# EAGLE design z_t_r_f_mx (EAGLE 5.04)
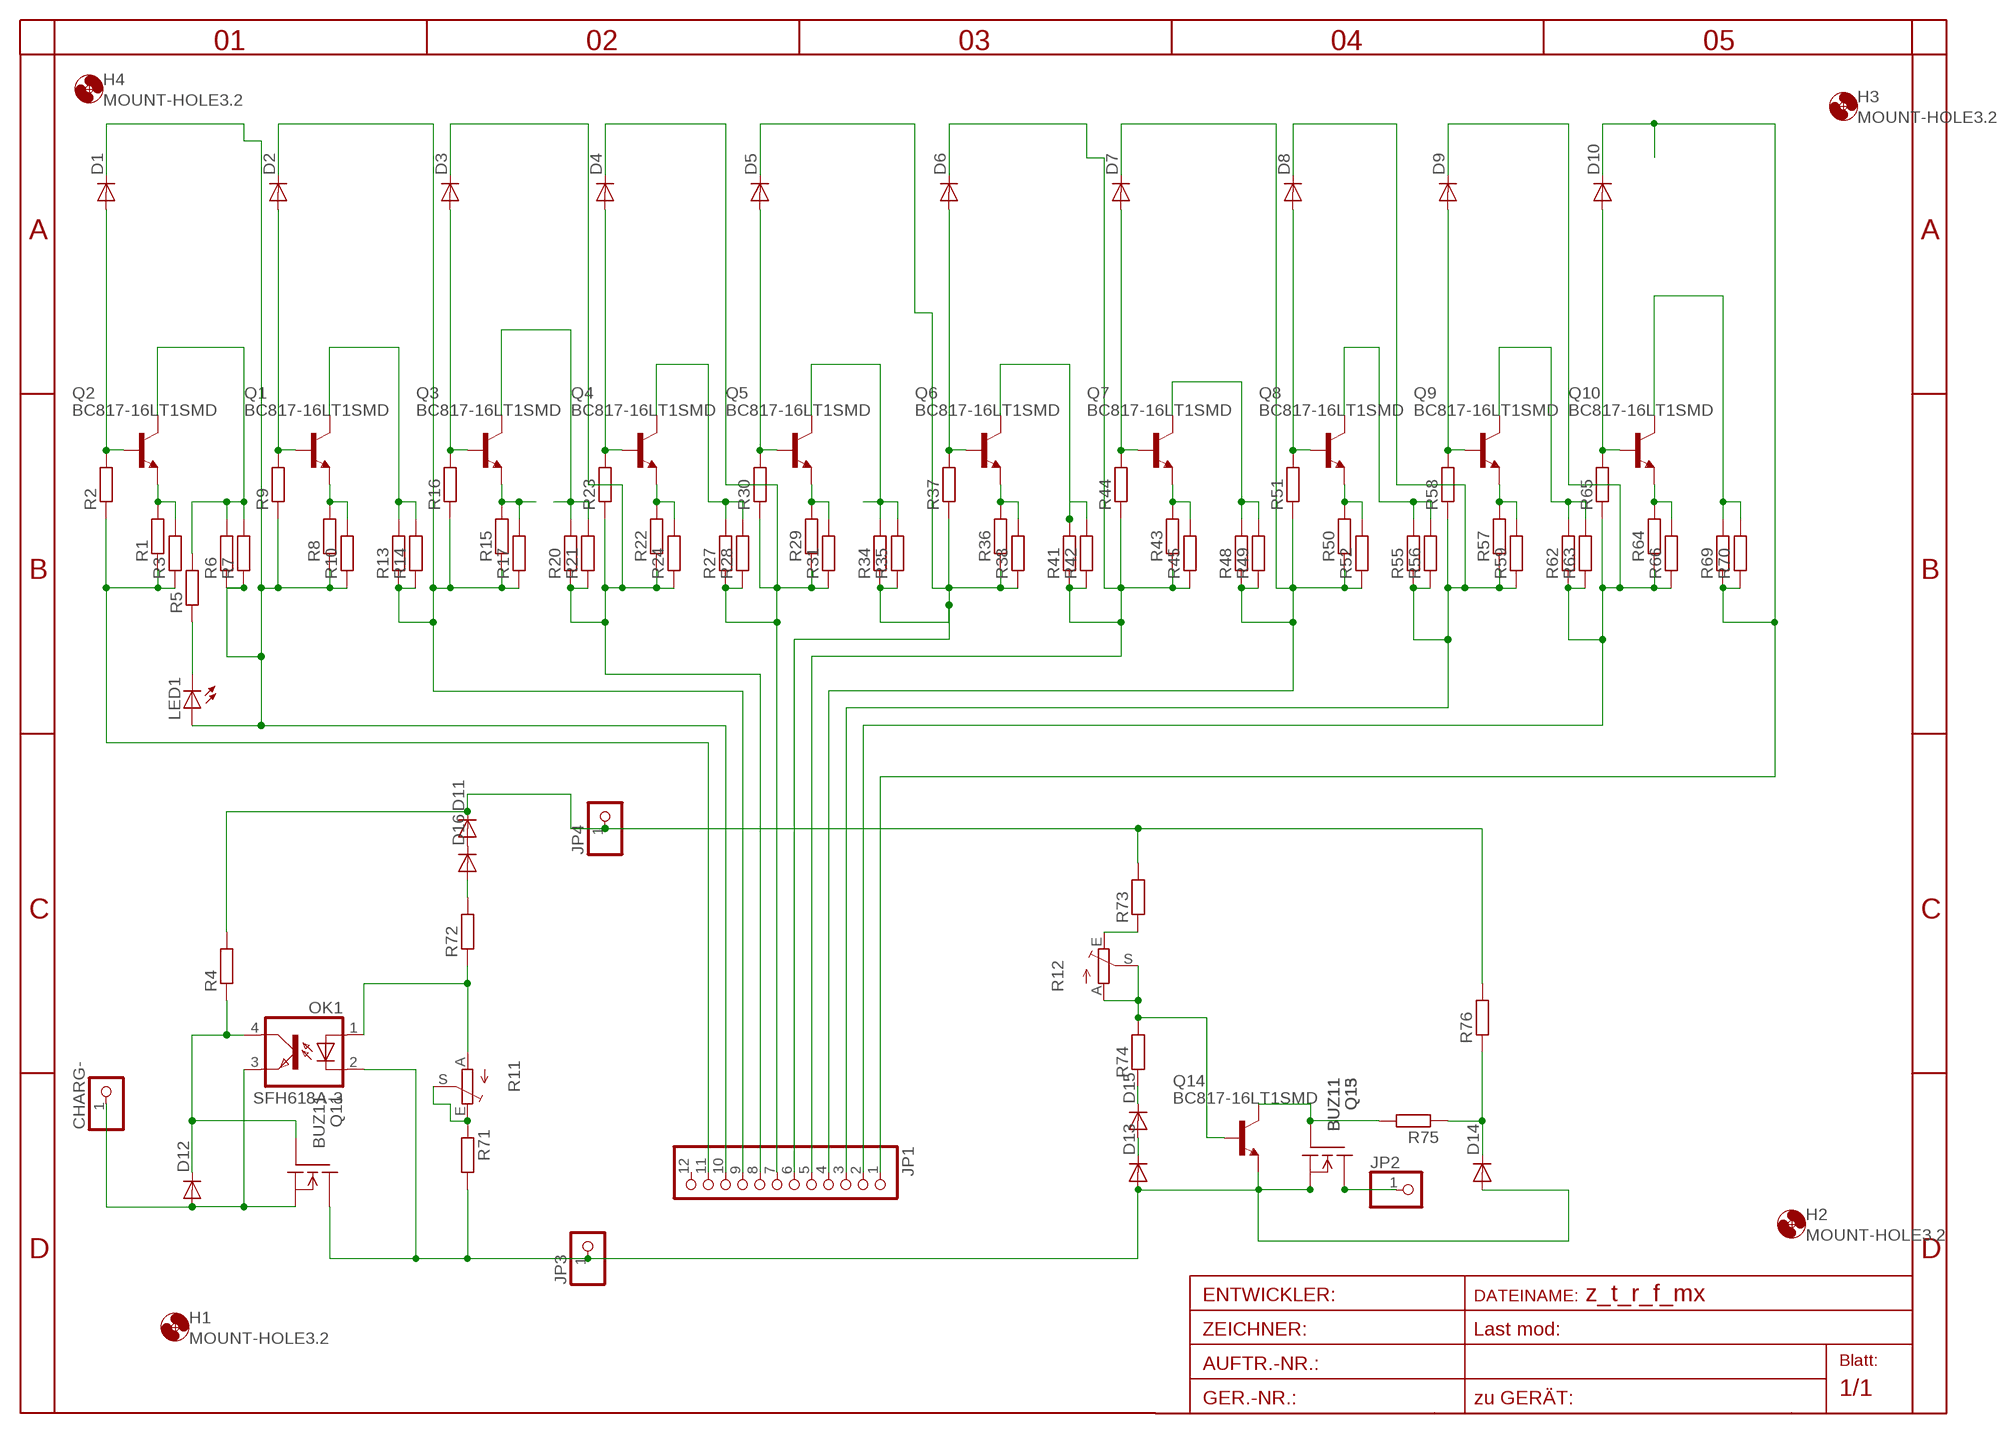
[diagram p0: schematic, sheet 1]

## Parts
CHARG-  PINHD-1X1  [1X01]
D1  DIODE-MINIMELF  [MINIMELF]
D2  DIODE-MINIMELF  [MINIMELF]
D3  DIODE-MINIMELF  [MINIMELF]
D4  DIODE-MINIMELF  [MINIMELF]
D5  DIODE-MINIMELF  [MINIMELF]
D6  DIODE-MINIMELF  [MINIMELF]
D7  DIODE-MINIMELF  [MINIMELF]
D8  DIODE-MINIMELF  [MINIMELF]
D9  DIODE-MINIMELF  [MINIMELF]
D10  DIODE-MINIMELF  [MINIMELF]
D11  DIODE-MINIMELF  [MINIMELF]
D12  DIODE-MINIMELF  [MINIMELF]
D13  DIODE-MINIMELF  [MINIMELF]
D14  DIODE-MINIMELF  [MINIMELF]
D15  DIODE-MINIMELF  [MINIMELF]
D16  DIODE-MINIMELF  [MINIMELF]
H1  MOUNT-HOLE3.2  [3,2]
H2  MOUNT-HOLE3.2  [3,2]
H3  MOUNT-HOLE3.2  [3,2]
H4  MOUNT-HOLE3.2  [3,2]
JP1  PINHD-1X12  [1X12]
JP2  PINHD-1X1  [1X01]
JP3  PINHD-1X1  [1X01]
JP4  PINHD-1X1  [1X01]
LED1  LEDCHIP-LED0805  [CHIP-LED0805]
OK1  SFH618A-3  [DIP4]
Q1  BC817-16LT1SMD  [SOT23-BEC]
Q2  BC817-16LT1SMD  [SOT23-BEC]
Q3  BC817-16LT1SMD  [SOT23-BEC]
Q4  BC817-16LT1SMD  [SOT23-BEC]
Q5  BC817-16LT1SMD  [SOT23-BEC]
Q6  BC817-16LT1SMD  [SOT23-BEC]
Q7  BC817-16LT1SMD  [SOT23-BEC]
Q8  BC817-16LT1SMD  [SOT23-BEC]
Q9  BC817-16LT1SMD  [SOT23-BEC]
Q10  BC817-16LT1SMD  [SOT23-BEC]
Q11  BUZ11  [TO220]
Q13  BUZ11  [TO220]
Q14  BC817-16LT1SMD  [SOT23-BEC]
Q15  BUZ11  [TO220]
R1  R-EU_R1206  [R1206]
R2  R-EU_R0805  [R0805]
R3  R-EU_R1206  [R1206]
R4  R-EU_R1206  [R1206]
R5  R-EU_R1206  [R1206]
R6  R-EU_R1206  [R1206]
R7  R-EU_R1206  [R1206]
R8  R-EU_R1206  [R1206]
R9  R-EU_R0805  [R0805]
R10  R-EU_R1206  [R1206]
R11  TRIM_EU-CA6V  [CA6V]
R12  TRIM_EU-CA6V  [CA6V]
R13  R-EU_R1206  [R1206]
R14  R-EU_R1206  [R1206]
R15  R-EU_R1206  [R1206]
R16  R-EU_R0805  [R0805]
R17  R-EU_R1206  [R1206]
R20  R-EU_R1206  [R1206]
R21  R-EU_R1206  [R1206]
R22  R-EU_R1206  [R1206]
R23  R-EU_R0805  [R0805]
R24  R-EU_R1206  [R1206]
R27  R-EU_R1206  [R1206]
R28  R-EU_R1206  [R1206]
R29  R-EU_R1206  [R1206]
R30  R-EU_R0805  [R0805]
R31  R-EU_R1206  [R1206]
R34  R-EU_R1206  [R1206]
R35  R-EU_R1206  [R1206]
R36  R-EU_R1206  [R1206]
R37  R-EU_R0805  [R0805]
R38  R-EU_R1206  [R1206]
R41  R-EU_R1206  [R1206]
R42  R-EU_R1206  [R1206]
R43  R-EU_R1206  [R1206]
R44  R-EU_R0805  [R0805]
R45  R-EU_R1206  [R1206]
R48  R-EU_R1206  [R1206]
R49  R-EU_R1206  [R1206]
R50  R-EU_R1206  [R1206]
R51  R-EU_R0805  [R0805]
R52  R-EU_R1206  [R1206]
R55  R-EU_R1206  [R1206]
R56  R-EU_R1206  [R1206]
R57  R-EU_R1206  [R1206]
R58  R-EU_R0805  [R0805]
R59  R-EU_R1206  [R1206]
R62  R-EU_R1206  [R1206]
R63  R-EU_R1206  [R1206]
R64  R-EU_R1206  [R1206]
R65  R-EU_R0805  [R0805]
R66  R-EU_R1206  [R1206]
R69  R-EU_R1206  [R1206]
R70  R-EU_R1206  [R1206]
R71  R-EU_R1206  [R1206]
R72  R-EU_R1206  [R1206]
R73  R-EU_R1206  [R1206]
R74  R-EU_R1206  [R1206]
R75  R-EU_R1206  [R1206]
R76  R-EU_R1206  [R1206]

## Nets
B1: D1.C JP1.10 LED1.A R6.1 R7.1 R8.1 R9.1 R10.1
B2: D2.C JP1.9 R13.1 R14.1 R15.1 R16.1 R17.1
B3: D3.C JP1.8 R20.1 R21.1 R22.1 R23.1 R24.1
B4: D4.C JP1.7 R27.1 R28.1 R29.1 R30.1 R31.1
B5: D5.C JP1.6 R34.1 R35.1 R36.1 R37.1 R38.1
B6: D6.C JP1.5 R41.1 R42.1 R43.1 R44.1 R45.1
B7: D7.C JP1.4 R48.1 R49.1 R50.1 R51.1 R52.1
B8: D8.C JP1.3 R55.1 R56.1 R57.1 R58.1 R59.1
B9: D9.C JP1.2 R62.1 R63.1 R64.1 R65.1 R66.1
B10: D10.C JP1.1 R69.1 R70.1
B-: JP1.11 R1.1 R2.1 R3.1
BATT+: D11.C JP4.1 R4.2 R73.2 R76.2
BATT-: D13.A D14.A JP3.1 OK1.2(C) Q11.2(D) Q13.3(S) Q14.E Q15.3(S) R71.2
CHAR-: CHARG-.1 D12.A OK1.3(EMIT) Q11.3(S)
D0: D1.A Q2.B R2.2
D1: D2.A Q1.B R9.2
D2: D3.A Q3.B R16.2
D3: D4.A Q4.B R23.2
D4: D5.A Q5.B R30.2
D5: D6.A Q6.B R37.2
D6: D7.A Q7.B R44.2
D7: D8.A Q8.B R51.2
D8: D9.A Q9.B R58.2
D9: D10.A Q10.B R65.2
MOTOR-: JP2.1 Q13.2(D) Q15.2(D)
N$1: Q2.C R5.2 R6.2 R7.2
N$2: Q2.E R1.2 R3.2
N$3: Q1.C R13.2 R14.2
N$4: Q1.E R8.2 R10.2
N$5: OK1.1(A) R11.A R72.1
N$6: Q3.C R20.2 R21.2
N$7: R11.E R11.S R71.1
N$8: Q4.E R22.2 R24.2
N$9: R12.E R73.1
N$10: Q5.C R34.2 R35.2
N$11: D12.C OK1.4(COL) Q11.1(G) R4.1
N$12: Q6.C R41.2 R42.2
N$13: Q14.B R12.A R12.S R74.2
N$14: Q7.E R43.2 R45.2
N$15: D13.C D15.A
N$16: Q8.C R55.2 R56.2
N$17: D15.C R74.1
N$18: Q9.E R57.2 R59.2
N$19: D11.A D16.C
N$20: Q10.C R69.2 R70.2
N$21: D16.A R72.2
N$23: Q5.E R29.2 R31.2
N$24: Q3.E R15.2 R17.2
N$25: Q13.1(G) Q14.C Q15.1(G) R75.2
N$26: LED1.C R5.1
N$27: D14.C R75.1 R76.1
N$29: Q4.C R27.2 R28.2
N$31: Q6.E R36.2 R38.2
N$33: Q7.C R48.2 R49.2
N$36: Q8.E R50.2 R52.2
N$37: Q9.C R62.2 R63.2
N$40: Q10.E R64.2 R66.2
Unconnected: JP1.12

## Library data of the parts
CHARG- JP2-JP4 = pinhead:PINHD-1X1: PIN HEADER
D1-D16 = diode-1:DIODE-: DIODE
H1-H4 = holes:MOUNT-HOLE: MOUNTING HOLE with drill center marker
JP1 = pinhead:PINHD-1X12: PIN HEADER
LED1 = led:LED: LED
OK1 = optocoupler:SFH618?*: Optocoupler, Phototransistor Output, Low Input Current Source: http://www.vishay.com/docs/83673/sfh618.pdf
Q1-Q10 Q14 = transistor-npn:BC817*: NPN Transistor
Q11 Q13 Q15 = transistor-fet:BUZ11: N-Channel Enhancement MOSFET 50V; 30A; 0,040Ohm
R1-R10 R13-R17 R20-R24 R27-R31 R34-R38 R41-R45 R48-R52 R55-R59 R62-R66 R69-R76 = rcl-2:R-EU_: RESISTOR, European symbol
R11 R12 = pot:TRIM_EU-: POTENTIOMETER

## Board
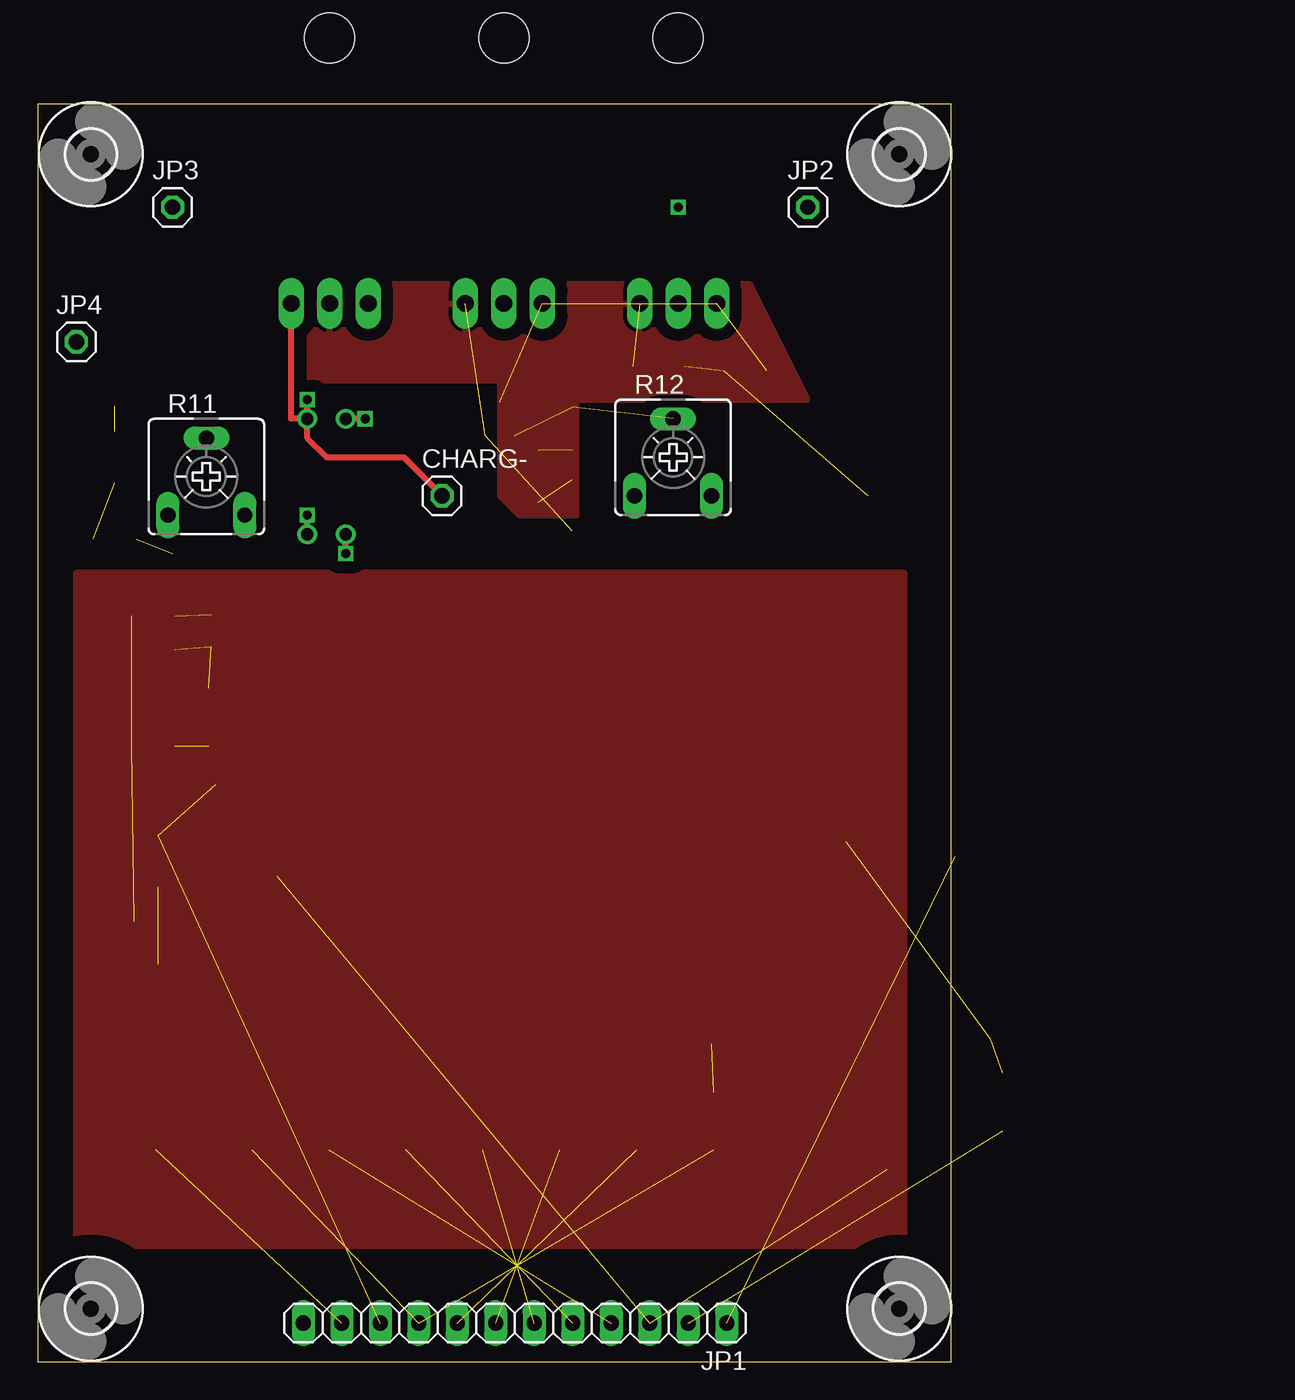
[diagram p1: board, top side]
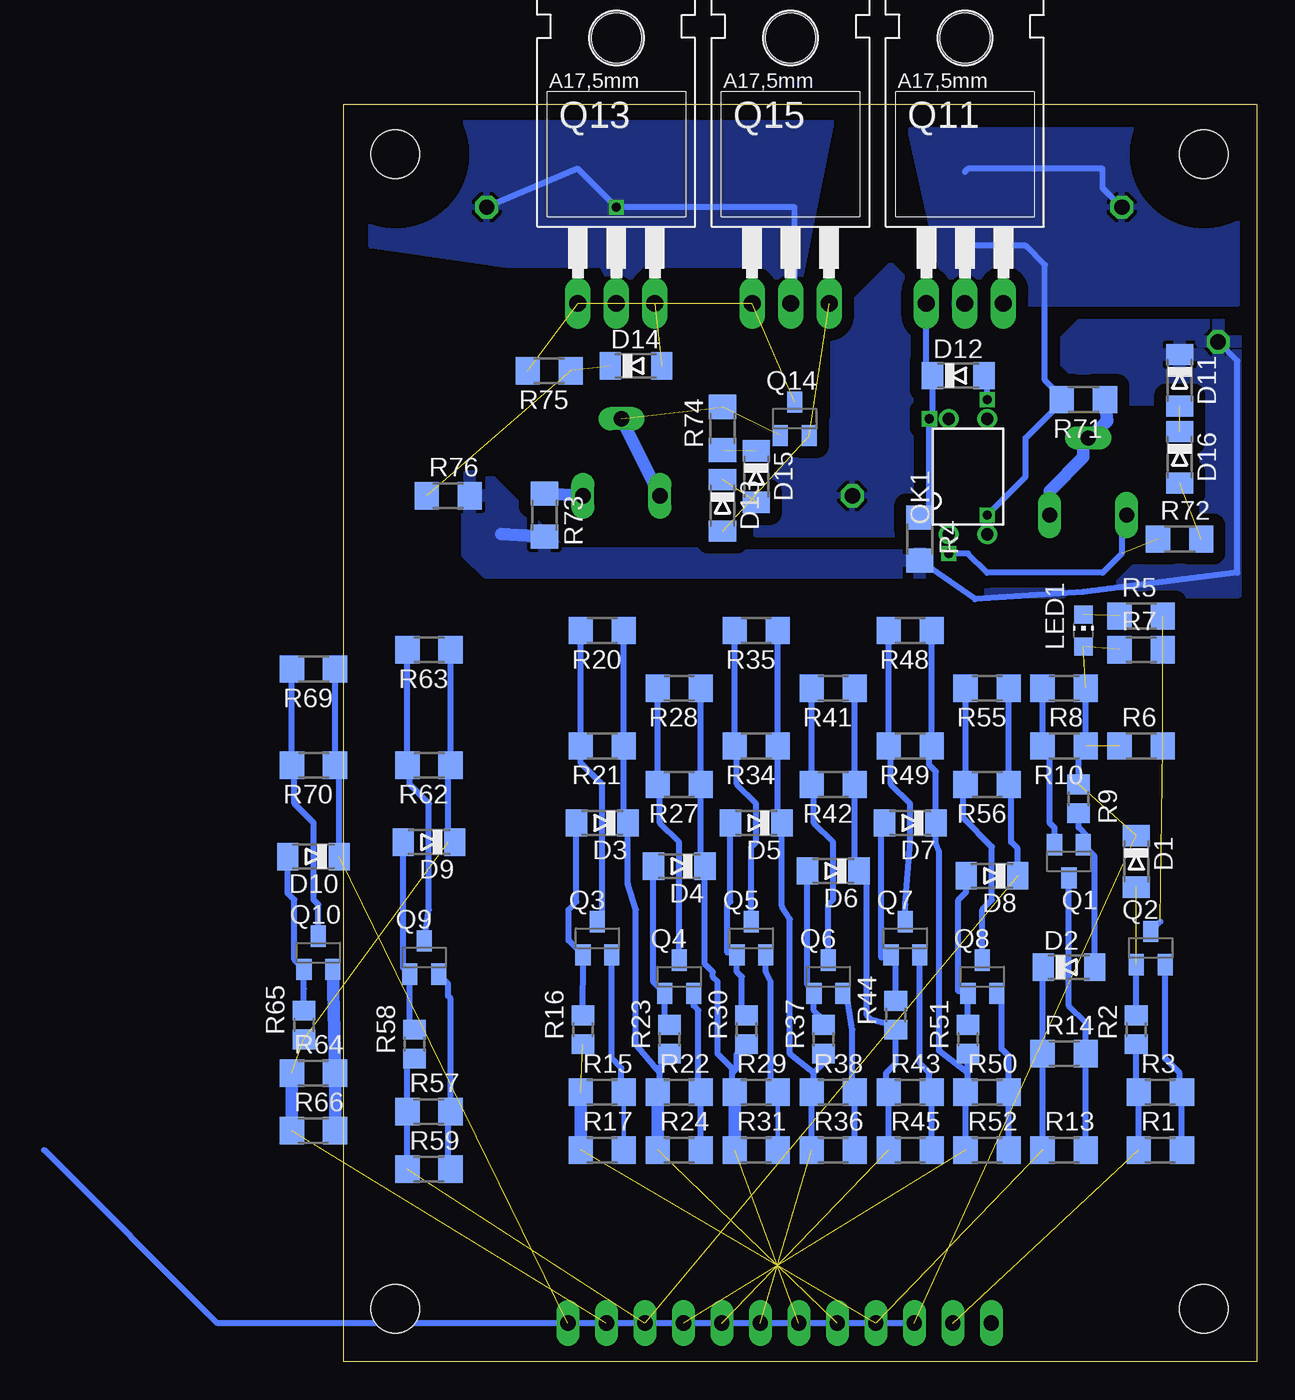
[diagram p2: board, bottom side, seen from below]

Size 60.25 x 83 mm. Coordinates in mm from the lower left corner, seen from the top.
Outline: 0,0 60.25,0 60.25,83 0,83 0,0
Copper layers (1*16): Top 0.035mm / dielectric 1.5mm / Bottom 0.035mm
Design rules "default": minimum track width 10mil, minimum drill 24mil, track to track 8mil, track to pad 8mil, pad to pad 8mil, via to via 8mil, smd to smd 8mil, copper to edge 40mil, drill to drill 8mil, minimum pad ring 10mil, minimum via ring 8mil, stop-mask expansion 4mil, vias tented up to drill 0mil, thermal gap 10mil

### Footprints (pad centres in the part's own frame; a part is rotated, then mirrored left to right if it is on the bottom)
1X01 = drill 1.016 octagon: 1 0,0
MINIMELF = smd 1.4 x 1.8: A 1.7,0; C -1.7,0
3,2 = hole 3.2: 0,0
1X12 = drill 1.016 long: 1 -13.97,0; 2 -11.43,0; 3 -8.89,0; 4 -6.35,0; 5 -3.81,0; 6 -1.27,0; 7 1.27,0; 8 3.81,0; 9 6.35,0; 10 8.89,0; 11 11.43,0; 12 13.97,0
CHIP-LED0805 = smd 1.2 x 1.2: A 0,-1.05; C 0,1.05
DIP4 = drill 0.8 round: 1 -1.27,-3.81; 2 1.27,-3.81; 3 1.27,3.81; 4 -1.27,3.81
SOT23-BEC = smd 1 x 1.4: B -0.95,-1.1; C 0,1.1; E 0.95,-1.1
TO220 = drill 1.118 long: 1 -2.54,-6.35; 2 0,-6.35; 3 2.54,-6.35 | hole 3.302: 0,11.176
R1206 = smd 1.6 x 1.803: 1 -1.422,0; 2 1.422,0
R0805 = smd 1.3 x 1.5: 1 -0.95,0; 2 0.95,0
CA6V = drill 1.016 long: A -2.54,-2.54; E 2.54,-2.54; S 0,2.54

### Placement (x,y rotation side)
CHARG-  26.67,57.15 0 top
D1  7.94,33.02 270 bottom
D2  12.38,26.04 0 bottom
D3  43.18,35.56 180 bottom
D4  38.1,32.7 180 bottom
D5  33.02,35.56 180 bottom
D6  27.94,32.38 180 bottom
D7  22.86,35.56 180 bottom
D8  17.46,32.07 180 bottom
D9  54.61,34.29 180 bottom
D10  62.23,33.34 180 bottom
D11  5.08,64.77 270 bottom
D12  19.68,65.09 0 bottom
D13  35.24,56.52 270 bottom
D14  40.96,65.72 0 bottom
D15  33.02,58.42 270 bottom
D16  5.08,59.69 270 bottom
H1  3.49,79.69 0 top
H2  56.83,79.69 0 top
H3  3.49,3.49 0 top
H4  56.83,3.49 0 top
JP1  31.48,2.54 180 top
JP2  50.8,76.2 0 top
JP3  8.89,76.2 0 top
JP4  2.54,67.31 0 top
LED1  11.43,48.26 0 bottom
OK1  19.05,58.42 0 bottom
Q1  12.38,33.02 180 bottom
Q2  6.99,27.3 0 bottom
Q3  43.5,27.94 0 bottom
Q4  38.1,25.4 0 bottom
Q5  33.34,27.94 0 bottom
Q6  28.26,25.4 0 bottom
Q7  23.18,27.94 0 bottom
Q8  18.1,25.4 0 bottom
Q9  54.93,26.67 0 bottom
Q10  61.91,26.99 0 bottom
Q11  19.25,76.2 0 bottom
Q13  42.25,76.2 0 bottom
Q14  30.48,62.23 0 bottom
Q15  30.75,76.2 0 bottom
R1  6.35,13.97 0 bottom
R2  7.94,21.91 90 bottom
R3  6.35,17.78 0 bottom
R4  22.23,54.29 270 bottom
R5  7.62,49.21 0 bottom
R6  7.62,40.64 0 bottom
R7  7.62,46.99 0 bottom
R8  12.7,44.45 180 bottom
R9  11.75,37.15 270 bottom
R10  12.7,40.64 180 bottom
R11  11.11,58.42 0 top
R12  41.91,59.69 0 top
R13  12.7,13.97 0 bottom
R14  12.7,20.32 0 bottom
R15  43.18,17.78 0 bottom
R16  44.45,21.91 90 bottom
R17  43.18,13.97 0 bottom
R20  43.18,48.26 180 bottom
R21  43.18,40.64 180 bottom
R22  38.1,17.78 0 bottom
R23  38.73,21.27 90 bottom
R24  38.1,13.97 0 bottom
R27  38.1,38.1 180 bottom
R28  38.1,44.45 180 bottom
R29  33.02,17.78 0 bottom
R30  33.66,21.91 90 bottom
R31  33.02,13.97 0 bottom
R34  33.02,40.64 180 bottom
R35  33.02,48.26 180 bottom
R36  27.94,13.97 0 bottom
R37  28.57,21.27 90 bottom
R38  27.94,17.78 0 bottom
R41  27.94,44.45 180 bottom
R42  27.94,38.1 180 bottom
R43  22.86,17.78 0 bottom
R44  23.81,22.86 90 bottom
R45  22.86,13.97 0 bottom
R48  22.86,48.26 180 bottom
R49  22.86,40.64 180 bottom
R50  17.78,17.78 0 bottom
R51  19.05,21.27 90 bottom
R52  17.78,13.97 0 bottom
R55  17.78,44.45 180 bottom
R56  17.78,38.1 180 bottom
R57  54.61,16.51 0 bottom
R58  55.56,20.95 90 bottom
R59  54.61,12.7 0 bottom
R62  54.61,39.37 180 bottom
R63  54.61,46.99 180 bottom
R64  62.23,19.05 0 bottom
R65  62.87,22.23 90 bottom
R66  62.23,15.24 0 bottom
R69  62.23,45.72 180 bottom
R70  62.23,39.37 180 bottom
R71  11.43,63.5 180 bottom
R72  5.08,54.29 0 bottom
R73  46.99,55.88 270 bottom
R74  35.24,61.59 90 bottom
R75  46.67,65.41 180 bottom
R76  53.34,57.15 0 bottom

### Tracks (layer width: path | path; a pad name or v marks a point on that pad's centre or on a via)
B1  (5 unrouted)
  Bottom 0.406: R9.1 11.75,40.17 R10.1 R8.1 | JP1.10 68.58,2.54 80.01,13.97
B2  (3 unrouted)
  Bottom 0.406: R13.1 R14.1 14.12,26 D2.C
  Bottom 0.813: R17.1 R15.1
B3  (1 unrouted)
  Bottom 0.406: 39.55,19.27 39.37,19.05 39.37,17.93 R22.1 | 39.55,19.27 40.96,20.95 40.96,29.84 41.48,31.55 D3.C 41.76,35.84 R21.1 R20.1 | R23.1 38.73,20.09 39.55,19.27
  Bottom 0.813: R24.1 R22.1
B4  (1 unrouted)
  Bottom 0.406: R28.1 R27.1 36.68,32.98 D4.C 36.4,26.24 35.88,25.72 35.88,25.4 35.56,25.08 35.56,20.32 34.61,19.37 34.61,19.05 | 34.61,19.05 34.61,17.95 R29.1 | R30.1 34.29,20.32 34.29,19.37 34.61,19.05
  Bottom 0.813: R31.1 R29.1
B5  (1 unrouted)
  Bottom 0.406: 29.21,19.05 30.8,20.32 30.8,29.21 31.32,30.05 D5.C 31.6,35.84 R34.1 R35.1 | 29.21,19.05 29.21,17.93 R38.1 R36.1 | R37.1 28.57,19.68 29.21,19.05
B6  (1 unrouted)
  Bottom 0.406: R41.1 R42.1 26.52,32.66 D6.C 25.72,32.38 25.72,22.86 25.4,22.54 24.13,22.23 R44.1 23.81,19.68 24.45,19.05 24.45,17.95 R43.1 R45.1
B7  (1 unrouted)
  Bottom 0.406: 19.05,19.05 R51.1 | 19.05,19.05 19.05,17.93 R50.1 R52.1 | 19.05,19.05 20.95,20.52 20.95,33.66 21.16,34.18 D7.C 21.16,38.94 21.59,39.37 21.59,40.49 R49.1 R48.1
B8  (2 unrouted)
  Bottom 0.406: R55.1 R56.1 16.19,37.93 16.19,34.29 15.76,33.86 D8.C | R58.1 56.03,19.85 R57.1 R59.1
B9  (3 unrouted)
  Bottom 0.406: D9.C 53.34,34.29 53.34,39.22 R62.1 R63.1 53.34,46.99
  Bottom 0.813: R66.1 R64.1
B10  (1 unrouted)
  Bottom 0.406: R69.1 R70.1 60.53,39.09 D10.C
B-  (1 unrouted)
  Bottom 0.406: R2.1 7.94,17.95 R3.1 R1.1
BATT+
  Bottom 0.406: R4.2 18.58,50.33 11.43,50.8 1.27,52.07 1.27,66.04 JP4.1
  Bottom 0.813: R73.2 49.85,54.61
  pour Bottom (isolate 0.813, rank 3): 1.27,69.85 10.16,69.85 12.7,67.31 12.7,66.04 10.16,63.5 3.81,63.5 3.81,53.34 45.72,53.34 50.8,58.42 52.07,58.42 52.07,53.34 50.8,52.07 19.05,52.07 17.78,50.8 1.27,50.8
BATT-  (via drill 0.6)  (3 unrouted)
  Top 0.406: OK1.2 v17.78,55.88
  Bottom 0.406: 19.25,78.54 19.05,78.74 10.16,78.74 10.16,77.47 JP3.1 | v17.78,55.88 15.24,58.42 15.24,60.96 12.85,63.35 R71.2 12.85,63.65 13.97,64.77 13.97,72.39 15.24,73.66 19.05,73.66 19.05,70.05 Q11.2
  pour Bottom (isolate 0.813, rank 2): 1.27,81.28 22.86,81.28 20.32,69.85 1.27,69.85
  pour Top (isolate 0.813, rank 2): 19.05,71.12 13.97,63.5 16.51,60.96 17.78,62.23 17.78,64.77 30.48,64.77 30.48,57.15 31.75,55.88 35.56,55.88 35.56,63.5 50.8,63.5 46.99,71.12
CHAR-  (via drill 0.6)
  Top 0.406: OK1.3 16.71,62.23 Q11.3 | OK1.3 17.78,60.96 19.05,59.69 24.13,59.69 CHARG-.1 | OK1.3 v17.78,63.5
  Bottom 0.406: v17.78,63.5 17.78,64.88 D12.A
  pour Bottom (isolate 0.813): 20.32,68.58 24.13,72.39 27.94,68.58 27.94,62.23 33.02,57.15 33.02,54.61 22.86,54.61 20.32,55.88
D0  (1 unrouted)
  Bottom 0.406: R2.2 Q2.B
D1
  Bottom 0.406: R9.2 11.75,35.24 11.11,34.61 11.11,34.44 Q1.B 10.68,33.37 D2.A
D2
  Bottom 0.406: D3.A 44.88,30.37 45.4,29.84 45.4,27.8 Q3.B R16.2
D3
  Bottom 0.406: D4.A 39.8,25.05 Q4.B 39.05,22.54 R23.2
D4
  Bottom 0.406: D5.A 34.72,30.37 34.92,30.16 34.92,26.99 34.44,26.99 Q5.B 34.29,25.71 33.97,25.4 33.97,23.18 R30.2
D5
  Bottom 0.406: R37.2 28.57,22.54 29.21,23.18 Q6.B 29.53,24.62 29.53,24.77 29.64,24.88 D6.A
D6
  Bottom 0.406: D7.A 24.77,35.56 24.77,26.67 24.13,26.67 Q7.B 23.81,26.84 R44.2
D7
  Bottom 0.406: D8.A 19.16,31 19.68,30.48 19.68,24.45 19.2,24.45 Q8.B 19.05,22.86 R51.2
D8
  Bottom 0.406: R58.2 55.88,21.91 Q9.B 56.31,26 D9.A
D9
  Bottom 0.406: R65.2 62.87,24.61 Q10.B 63.5,26.52 63.5,30.48 63.93,30.91 D10.A
MOTOR-  (via drill 0.6)
  Top 0.406: Q15.2 30.48,69.85
  Bottom 0.406: 30.48,69.85 30.48,76.2 v42.25,76.2 44.79,78.74 JP2.1
  pour Bottom (isolate 0.813): 58.42,73.66 58.42,82.55 27.94,82.55 30.48,69.85 33.02,72.39 40.64,72.39 41.91,69.85 43.18,72.39 49.53,72.39
N$1  (3 unrouted)
  Bottom 0.406: Q2.C 6.35,29.04
N$2
  Bottom 0.406: Q2.E 6.04,20 5.08,19.05 5.08,17.93 R3.2 R1.2
N$3
  Bottom 0.406: R13.2 R14.2 11.28,22.39 12.38,23.5 Q1.C
N$4
  Bottom 0.406: Q1.E 13.33,35.24 13.65,35.56 13.65,40.32 13.8,40.32 R10.2 14.12,44.3 13.97,44.45 R8.2
N$5  (via drill 0.6)  (1 unrouted)
  Top 0.406: v20.32,53.34 OK1.1
  Bottom 0.406: v20.32,53.34 19.05,53.34 17.78,52.07 10.16,52.07 8.89,53.34 8.89,55.56 R11.A
N$6
  Bottom 0.406: R20.2 44.6,40.79 44.45,40.64 R21.2 44.6,39.52 43.18,38.1 43.18,29.21 43.33,29.21 Q3.C
N$7
  Bottom 0.406: 11.43,60.64 R11.S
  Bottom 0.813: R11.E 13.65,57.47 11.43,59.69 11.43,60.64 | R11.S 9.84,62.06 R71.1
N$8
  Bottom 0.406: Q4.E 37.15,23.5 36.83,23.18 36.83,17.93 R22.2 R24.2
N$9
  Bottom 0.813: R12.E R73.1
N$10
  Bottom 0.406: R35.2 R34.2 34.29,40.49 34.29,38.1 33.02,36.83 33.02,34.29 33.34,33.97 Q5.C
N$11  (via drill 0.6)
  Top 0.406: v21.59,62.23 OK1.4
  Bottom 0.406: Q11.1 21.79,65.09 D12.C 21.39,62.23 v21.59,62.23 21.59,55.72 R4.1
N$12
  Bottom 0.406: Q6.C 28.26,30.16 27.94,30.48 27.94,34.29 29.21,35.56 29.21,37.95 R42.2 R41.2
N$13  (2 unrouted)
  Bottom 0.813: R12.A R12.S
N$14
  Bottom 0.406: Q7.E 22.23,19.69 21.59,19.05 21.59,17.93 R43.2 R45.2
N$15  (1 unrouted)
N$16
  Bottom 0.406: Q8.C 18.1,29.84 17.46,30.48 17.46,33.97 19.37,35.88 19.37,37.93 R56.2 R55.2
N$17  (1 unrouted)
N$18
  Bottom 0.406: Q9.E 53.34,24.93 53.34,24.13 53.19,23.98 R57.2 53.34,16.51 53.34,12.85 R59.2
N$19  (1 unrouted)
N$20
  Bottom 0.406: R69.2 R70.2 63.5,39.22 63.5,36.83 62.23,35.56 62.23,30.48 61.91,30.16 Q10.C
N$21  (1 unrouted)
N$22
  pour Top (isolate 0.813, rank 2): 2.54,52.07 57.15,52.07 57.15,7.62 2.54,7.62
N$23
  Bottom 0.305: R31.2 R29.2
  Bottom 0.406: Q5.E 32.39,25.72 32.07,25.08 32.07,17.93 R29.2
N$24
  Bottom 0.305: R17.2 R15.2
  Bottom 0.406: Q3.E 42.55,20 41.91,19.37 41.91,17.93 R15.2
N$25  (3 unrouted)
N$26  (1 unrouted)
N$27  (2 unrouted)
N$29
  Bottom 0.406: R28.2 R27.2 39.37,37.95 39.37,35.56 38.1,34.29 Q4.C
N$31
  Bottom 0.406: Q6.E 26.99,23.82 26.67,21.91 26.67,17.93 R38.2 R36.2
N$33
  Bottom 0.406: Q7.C 23.18,30.16 22.86,34.29 22.86,36.83 24.13,38.1 24.13,40.49 R49.2 R48.2
N$36
  Bottom 0.406: Q8.E 16.83,23.98 16.83,20.64 16.36,20.17 R50.2 R52.2
N$37
  Bottom 0.406: Q9.C 54.61,29.84 54.61,36.83 55.88,38.1 55.88,39.22 R62.2 R63.2
N$40
  Bottom 0.813: Q10.E R64.2 R66.2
